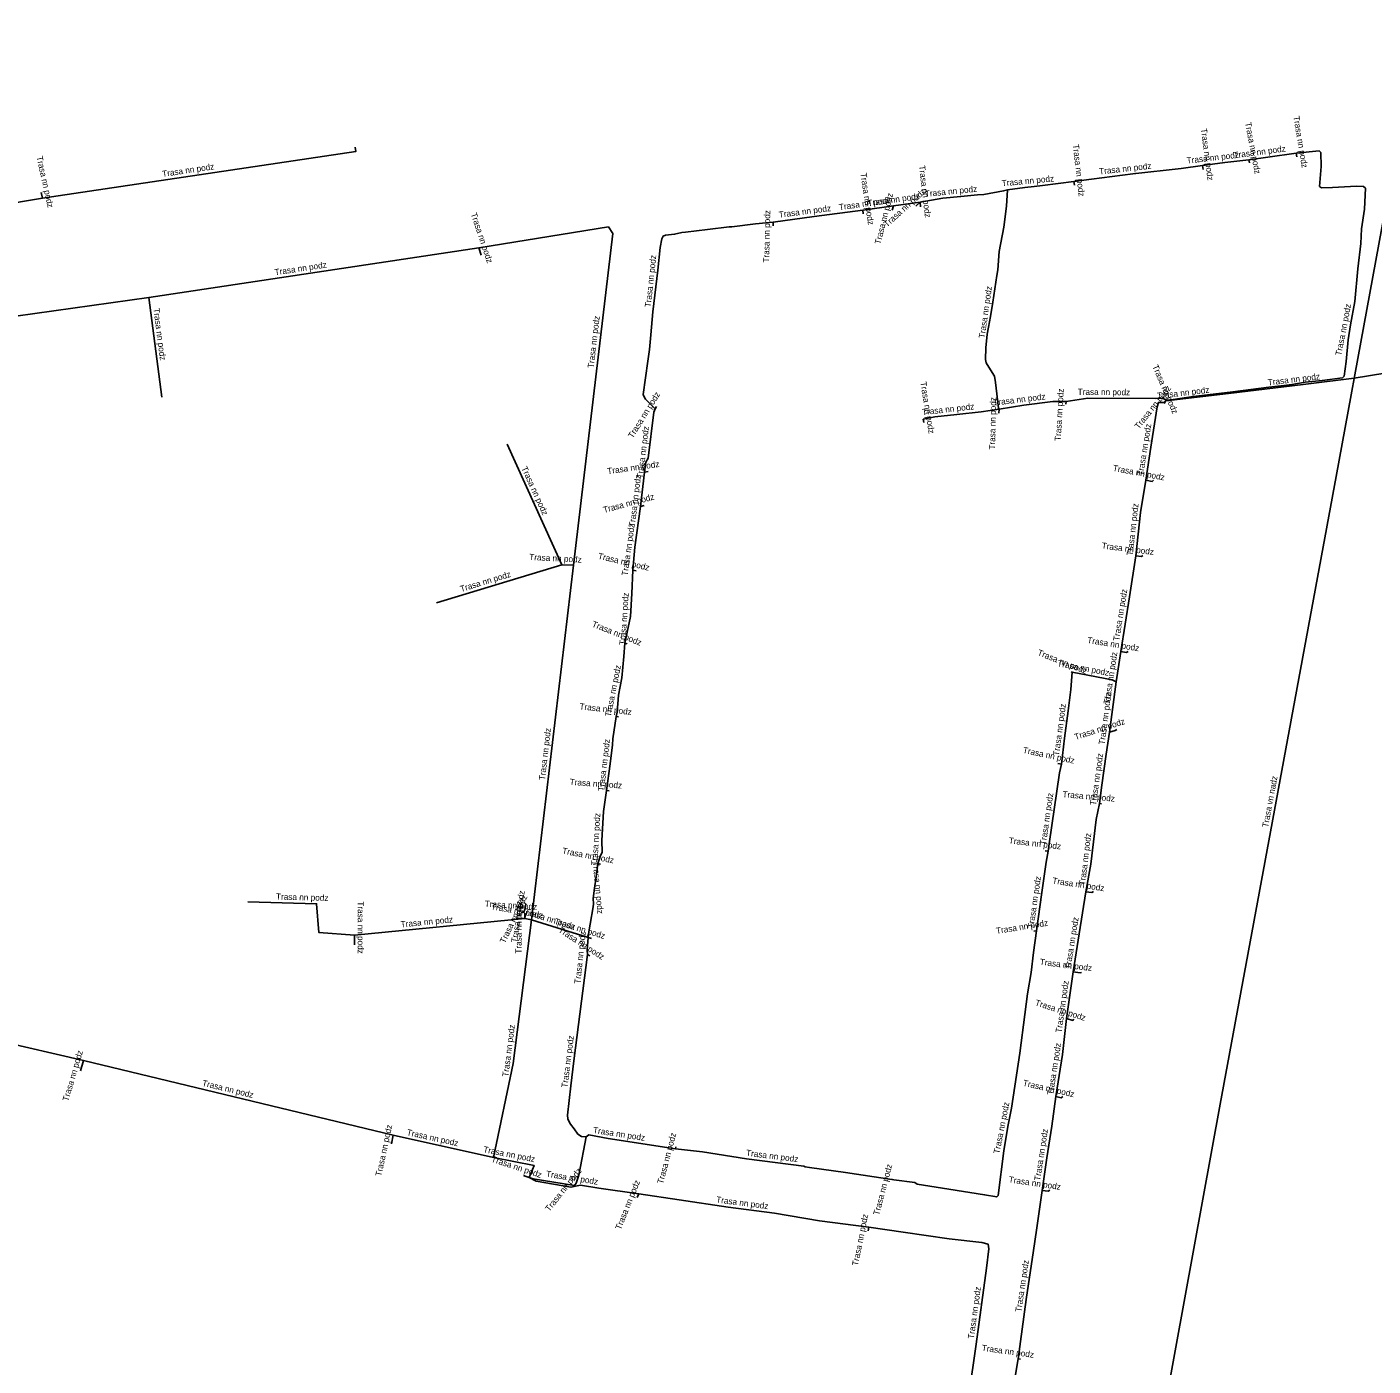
# Model space of a CAD drawing. Extents: x -724876 to -714160, y -1042389 to -1039790.
# Drawn here: x -719777.8 to -719558.8, y -1041292.4 to -1041074.3 of the extents above; entities that cross this region are included whole.
import ezdxf

# ---------------------------------------------------------------- set-up
doc = ezdxf.new("R2010")
doc.units = 0
for name, color, linetype in [('Level 11', 7, 'Continuous'), ('Level 20', 7, 'Continuous'), ('Level 21', 7, 'Continuous')]:
    doc.layers.add(name, color=color, linetype=linetype)

msp = doc.modelspace()

# ---------------------------------------------------------------- linework, layer by layer
at = {"layer": 'Level 11'}
for p, q in [((-719578.95, -1041095.98), (-719578.86, -1041096.47)), ((-719571.25, -1041094.92), (-719571.15, -1041095.5)), ((-719586.5, -1041096.91), (-719586.42, -1041097.55)), ((-719607.44, -1041099.49), (-719607.36, -1041100.13)), ((-719814.8, -1041109), (-719775.3, -1041102.2)), ((-719775.3, -1041102.2), (-719775.5, -1041101.3)), ((-719636.82, -1041103.47), (-719632.47, -1041102.86)), ((-719632.47, -1041102.86), (-719633.18, -1041103.5)), ((-719632.39, -1041103.63), (-719632.47, -1041102.86)), ((-719641.8, -1041104.17), (-719636.82, -1041103.47)), ((-719641.8, -1041104.17), (-719641.71, -1041104.77)), ((-719636.82, -1041103.47), (-719637, -1041104.2)), ((-719656.39, -1041106.15), (-719656.4, -1041106.75)), ((-719758, -1041118.4), (-719704.3, -1041110.3)), ((-719704.3, -1041110.3), (-719703.9, -1041111.5)), ((-719816.9, -1041126.7), (-719758, -1041118.4)), ((-719758, -1041118.4), (-719755.9, -1041134.6)), ((-719608.7, -1041135.31), (-719608.73, -1041135.76)), ((-719592.42, -1041135.09), (-719592.72, -1041135.47)), ((-719675.6, -1041136.52), (-719675.38, -1041136.16)), ((-719631.96, -1041138.18), (-719631.86, -1041138.76)), ((-719619.65, -1041137.23), (-719619.63, -1041136.57)), ((-719690.8, -1041161.9), (-719699.7, -1041142.3)), ((-719677.99, -1041152.42), (-719677.3, -1041146.82)), ((-719677.3, -1041146.82), (-719676.74, -1041146.74)), ((-719677.99, -1041152.42), (-719677.4, -1041152.26)), ((-719690.8, -1041161.9), (-719711.2, -1041168.1)), ((-719688.9, -1041162), (-719695.7, -1041219.7)), ((-719688.9, -1041162), (-719690.8, -1041161.9)), ((-719679.21, -1041162.79), (-719678.7, -1041162.92)), ((-719680.5, -1041174.66), (-719680.12, -1041174.81)), ((-719599.83, -1041176.03), (-719600.58, -1041180.97)), ((-719607.71, -1041179.4), (-719607.89, -1041179.33)), ((-719600.58, -1041180.97), (-719601.67, -1041189.19)), ((-719681.91, -1041186.61), (-719681.57, -1041186.65)), ((-719609.46, -1041194.38), (-719610.07, -1041194.25)), ((-719683.51, -1041198.67), (-719683.07, -1041198.7)), ((-719603.3, -1041200.78), (-719602.93, -1041200.81)), ((-719684.9, -1041210.56), (-719684.51, -1041210.64)), ((-719611.65, -1041208.52), (-719612.13, -1041208.47)), ((-719697, -1041218.48), (-719697.22, -1041218.46)), ((-719696.8, -1041219.5), (-719724.5, -1041222.2)), ((-719695.7, -1041219.7), (-719696.8, -1041219.5)), ((-719695.7, -1041219.7), (-719686.47, -1041222.6)), ((-719613.51, -1041221.49), (-719613.98, -1041221.56)), ((-719724.5, -1041222.2), (-719724.5, -1041223.8)), ((-719686.47, -1041222.6), (-719685.95, -1041222.76)), ((-719686.61, -1041225.35), (-719686.23, -1041225.59)), ((-719607.56, -1041228.21), (-719608.62, -1041235.8)), ((-719768.6, -1041242.6), (-719792.4, -1041237.2)), ((-719768.6, -1041242.6), (-719769.1, -1041244.3)), ((-719718.2, -1041254.8), (-719768.6, -1041242.6)), ((-719718.2, -1041254.8), (-719718.5, -1041256.2)), ((-719701.9, -1041258.4), (-719718.2, -1041254.8)), ((-719672.28, -1041257), (-719672.2, -1041256.7)), ((-719637.09, -1041262.01), (-719637.06, -1041261.87)), ((-719678.26, -1041264.31), (-719678.51, -1041264.92)), ((-719640.8, -1041269.75), (-719640.92, -1041270.36)), ((-719616.52, -1041291.2), (-719616.12, -1041291.25))]:
    msp.add_line(p, q, dxfattribs=at)
for points in [[(-719775.3, -1041102.2), (-719724.3, -1041094.6), (-719724.4, -1041093.9)], [(-719592.42, -1041135.09), (-719591.31, -1041134.98), (-719588.04, -1041134.51), (-719581.58, -1041133.73), (-719575.7, -1041132.98), (-719573.29, -1041132.74), (-719572, -1041132.58), (-719569.78, -1041132.17), (-719567.05, -1041131.89), (-719563.74, -1041131.45), (-719563.47, -1041131.2), (-719563.14, -1041128.79), (-719562.78, -1041125.31), (-719562.44, -1041122.86), (-719561.71, -1041119.03), (-719561.25, -1041113.73), (-719560.76, -1041109.59), (-719560.61, -1041107.22), (-719560.17, -1041104), (-719559.97, -1041100.62), (-719560.29, -1041100.3), (-719561.43, -1041100.29), (-719565.33, -1041100.5), (-719567.17, -1041100.53), (-719567.45, -1041100.3), (-719567.22, -1041097.06), (-719567.25, -1041094.8), (-719567.53, -1041094.49), (-719571.25, -1041094.92)], [(-719578.95, -1041095.98), (-719582.88, -1041096.42), (-719586.5, -1041096.91)], [(-719571.25, -1041094.92), (-719575.9, -1041095.53), (-719578.95, -1041095.98)], [(-719586.5, -1041096.91), (-719590, -1041097.41), (-719597.83, -1041098.28), (-719604.58, -1041099.12), (-719607.44, -1041099.49)], [(-719632.47, -1041102.86), (-719628.75, -1041102.23), (-719625.82, -1041101.95), (-719623.14, -1041101.68), (-719622.09, -1041101.61), (-719618.88, -1041101.03), (-719618.23, -1041100.89)], [(-719618.23, -1041100.89), (-719618.43, -1041103.5), (-719618.85, -1041106.96), (-719619.58, -1041110.92), (-719619.84, -1041113.87), (-719620, -1041114.84), (-719620.61, -1041119.16), (-719621.04, -1041121.51), (-719621.33, -1041123.23), (-719621.55, -1041124.34), (-719621.8, -1041126.58), (-719621.82, -1041128.47), (-719621.7, -1041129.03), (-719620.74, -1041130.63), (-719620.39, -1041131.18), (-719620.21, -1041132.26), (-719619.71, -1041136.39), (-719619.63, -1041136.57)], [(-719607.44, -1041099.49), (-719612.53, -1041100.18), (-719613.89, -1041100.31), (-719615.4, -1041100.48), (-719618.23, -1041100.89)], [(-719656.39, -1041106.15), (-719649.73, -1041105.19), (-719641.8, -1041104.17)], [(-719704.3, -1041110.3), (-719683.2, -1041106.9), (-719682.5, -1041108), (-719688.9, -1041162)], [(-719675.6, -1041136.52), (-719677.17, -1041134.96), (-719677.4, -1041134.59), (-719677.52, -1041134.21), (-719676.78, -1041128.74), (-719676.53, -1041126.85), (-719676.31, -1041124.46), (-719675.95, -1041120.72), (-719675.15, -1041113.94), (-719674.77, -1041110.28), (-719674.5, -1041108.87), (-719674.27, -1041108.41), (-719673.9, -1041108.26), (-719672.43, -1041108.1), (-719671.25, -1041107.84), (-719670.65, -1041107.75), (-719667.05, -1041107.34), (-719663.57, -1041106.89), (-719663.12, -1041106.88), (-719659.28, -1041106.39), (-719656.39, -1041106.15)], [(-719582.27, -1041134.04), (-719570.12, -1041132.54), (-719561.83, -1041131.55), (-719556.83, -1041130.71)], [(-719619.63, -1041136.57), (-719615.6, -1041135.93), (-719610.88, -1041135.34), (-719608.7, -1041135.31)], [(-719608.7, -1041135.31), (-719605.17, -1041134.77), (-719594.16, -1041134.86), (-719592.97, -1041134.81), (-719592.42, -1041135.09)], [(-719592.72, -1041135.47), (-719593.68, -1041135.49), (-719593.87, -1041136.2), (-719594.92, -1041142.74), (-719595.75, -1041148.14)], [(-719582.27, -1041134.04), (-719592.46, -1041135.24), (-719592.72, -1041135.47)], [(-719592.72, -1041135.47), (-719592.72, -1041135.48), (-719592.65, -1041135.65)], [(-719677.3, -1041146.82), (-719677.11, -1041145.23), (-719676.7, -1041144.54), (-719675.81, -1041137.05), (-719675.6, -1041136.52)], [(-719619.63, -1041136.57), (-719622.53, -1041136.99), (-719626.5, -1041137.43), (-719630.05, -1041137.82), (-719631.96, -1041138.18)], [(-719595.75, -1041148.14), (-719596.58, -1041153.42), (-719597.38, -1041160.46)], [(-719595.75, -1041148.14), (-719594.73, -1041148.33), (-719594.47, -1041148.13)], [(-719679.21, -1041162.79), (-719678.91, -1041159.06), (-719677.99, -1041152.42)], [(-719597.38, -1041160.46), (-719598.42, -1041167.12), (-719599.83, -1041176.03)], [(-719597.38, -1041160.46), (-719596.45, -1041160.58), (-719596.25, -1041160.41)], [(-719680.5, -1041174.66), (-719679.62, -1041170.32), (-719679.39, -1041166.6), (-719679.21, -1041162.79)], [(-719681.91, -1041186.61), (-719681.79, -1041185.91), (-719681.58, -1041183.12), (-719681.02, -1041180.3), (-719680.68, -1041176.84), (-719680.5, -1041174.66)], [(-719599.83, -1041176.03), (-719598.91, -1041176.18), (-719598.59, -1041176.02)], [(-719609.46, -1041194.38), (-719608.97, -1041190.17), (-719608.37, -1041185.68), (-719607.94, -1041182.22), (-719607.71, -1041179.4)], [(-719600.58, -1041180.97), (-719601.22, -1041180.63), (-719607.71, -1041179.4)], [(-719683.51, -1041198.67), (-719682.89, -1041194.31), (-719682.53, -1041191.23), (-719682.48, -1041190.23), (-719681.91, -1041186.61)], [(-719601.67, -1041189.19), (-719602.18, -1041192.76), (-719602.89, -1041197.8), (-719603.3, -1041200.78)], [(-719601.67, -1041189.19), (-719600.7, -1041188.88), (-719600.43, -1041188.73)], [(-719611.65, -1041208.52), (-719611.47, -1041207.35), (-719609.79, -1041195.78), (-719609.46, -1041194.38)], [(-719684.9, -1041210.56), (-719684.56, -1041209.43), (-719684.24, -1041208.68), (-719684.26, -1041206.81), (-719683.99, -1041202.11), (-719683.51, -1041198.67)], [(-719603.3, -1041200.78), (-719603.84, -1041203.41), (-719604.7, -1041210.65), (-719605.5, -1041215.14)], [(-719686.47, -1041222.6), (-719686.36, -1041221.65), (-719686.14, -1041220.42), (-719685.66, -1041217.59), (-719685.62, -1041217.14), (-719685.7, -1041216.24), (-719685.44, -1041214.54), (-719685.18, -1041212.72), (-719684.9, -1041210.56)], [(-719613.51, -1041221.49), (-719612.65, -1041215.25), (-719611.93, -1041210.31), (-719611.65, -1041208.52)], [(-719724.5, -1041222.2), (-719730.3, -1041221.8), (-719730.7, -1041217.1), (-719741.9, -1041216.8)], [(-719696.93, -1041216.91), (-719696.61, -1041217.17), (-719696.72, -1041217.9)], [(-719605.5, -1041215.14), (-719606.58, -1041221.99), (-719607.56, -1041228.21)], [(-719605.5, -1041215.14), (-719604.55, -1041215.28), (-719604.25, -1041215.13)], [(-719696.72, -1041217.9), (-719696.91, -1041218.3), (-719697, -1041218.48)], [(-719697, -1041218.48), (-719696.8, -1041218.7), (-719696.8, -1041219.5)], [(-719701.9, -1041258.4), (-719698.7, -1041243.1), (-719695.7, -1041219.7)], [(-719637.09, -1041262.01), (-719636.76, -1041262.05), (-719633.33, -1041262.51), (-719632.96, -1041262.78), (-719627.79, -1041263.57), (-719621.98, -1041264.47), (-719620.01, -1041264.83), (-719619.78, -1041264.62), (-719618.86, -1041257.34), (-719618.18, -1041253.36), (-719617.6, -1041250.39), (-719616.24, -1041241.44), (-719615.43, -1041235.14), (-719614.99, -1041231.75), (-719614.41, -1041228.27), (-719614, -1041225.03), (-719613.51, -1041221.49)], [(-719686.61, -1041225.35), (-719686.68, -1041224.63), (-719686.47, -1041222.6)], [(-719686.84, -1041255.04), (-719687.56, -1041254.99), (-719688.16, -1041254.6), (-719688.77, -1041253.77), (-719689.39, -1041252.98), (-719689.61, -1041252.61), (-719689.82, -1041252.11), (-719689.86, -1041251.52), (-719689.31, -1041246.76), (-719688.81, -1041242.69), (-719686.61, -1041225.35)], [(-719607.56, -1041228.21), (-719606.42, -1041228.35), (-719606.18, -1041228.27)], [(-719608.62, -1041235.8), (-719609.3, -1041241.66), (-719610.37, -1041248.48)], [(-719608.62, -1041235.8), (-719607.63, -1041236.11), (-719607.44, -1041235.92)], [(-719610.37, -1041248.48), (-719611.06, -1041253.3), (-719611.85, -1041258.45), (-719612.61, -1041263.78)], [(-719610.37, -1041248.48), (-719609.49, -1041248.68), (-719609.26, -1041248.51)], [(-719696.09, -1041261.69), (-719695.42, -1041261.91), (-719688.73, -1041262.99), (-719688.44, -1041262.62), (-719688.13, -1041261.62), (-719687.97, -1041261.03), (-719686.84, -1041255.04)], [(-719686.84, -1041255.04), (-719686.38, -1041254.73), (-719683.22, -1041255.32), (-719672.28, -1041257)], [(-719696.09, -1041261.69), (-719695.3, -1041259.7), (-719701.9, -1041258.4)], [(-719672.28, -1041257), (-719667.91, -1041257.48), (-719660.72, -1041258.64), (-719651.4, -1041259.82), (-719651.19, -1041259.93), (-719650.47, -1041260.05), (-719644.62, -1041260.88), (-719637.09, -1041262.01)], [(-719696.99, -1041261.37), (-719696.57, -1041261.53), (-719696.09, -1041261.69)], [(-719678.26, -1041264.31), (-719684.77, -1041263.39), (-719687.73, -1041262.93), (-719689.3, -1041263.27), (-719694.96, -1041262.26), (-719696.09, -1041261.69)], [(-719640.8, -1041269.75), (-719648.86, -1041268.72), (-719656.18, -1041267.48), (-719663.7, -1041266.5), (-719671.7, -1041265.3), (-719678.26, -1041264.31)], [(-719612.61, -1041263.78), (-719613.55, -1041270.23), (-719614, -1041273.58), (-719615.19, -1041281.56), (-719616.52, -1041291.2)], [(-719612.61, -1041263.78), (-719611.62, -1041263.92), (-719611.34, -1041263.76)], [(-719626.73, -1041310.38), (-719626.61, -1041308.97), (-719625.98, -1041307.8), (-719625.59, -1041304.87), (-719624.53, -1041297.11), (-719623.34, -1041288.81), (-719621.64, -1041276.46), (-719621.31, -1041273.31), (-719621.4, -1041272.55), (-719622.44, -1041272.28), (-719627.73, -1041271.64), (-719635.22, -1041270.6), (-719640.8, -1041269.75)], [(-719616.52, -1041291.2), (-719616.98, -1041294.05), (-719617.64, -1041298.87), (-719619.07, -1041308.2), (-719619.55, -1041311.4)]]:
    msp.add_lwpolyline(points, dxfattribs=at)
at = {"layer": 'Level 21'}
for p, q in [((-719564.76, -1041147.56), (-719545.11, -1041040.19)), ((-719583.65, -1041249.73), (-719564.76, -1041147.56)), ((-719602.49, -1041353.09), (-719583.65, -1041249.73))]:
    msp.add_line(p, q, dxfattribs=at)

# ---------------------------------------------------------------- texts
at = {"layer": 'Level 20'}
for s, rotation, p in [('Trasa nn podz', 280.7736, (-719579.59, -1041089.95)), ('Trasa nn podz', 279.5105, (-719571.74, -1041088.93)), ('Trasa nn podz', 277.5709, (-719586.79, -1041090.93)), ('Trasa nn podz', 276.5549, (-719607.62, -1041093.51)), ('Trasa nn podz', 7.4646, (-719581.4, -1041095.74)), ('Trasa nn podz', 282.5288, (-719776.28, -1041095.5)), ('Trasa nn podz', 8.4758, (-719755.74, -1041098.78)), ('Trasa nn podz', 6.304, (-719603.28, -1041098.37)), ('Trasa nn podz', 6.3754, (-719589.04, -1041096.6)), ('Trasa nn podz', 278.4201, (-719642.18, -1041098.18)), ('Trasa nn podz', 276.6839, (-719632.66, -1041096.95)), ('Trasa nn podz', 5.3846, (-719619.14, -1041100.3)), ('Trasa nn podz', 41.8036, (-719637.85, -1041107)), ('Trasa nn podz', 5.6259, (-719631.65, -1041102.02)), ('Trasa nn podz', 7.9369, (-719645.61, -1041104.19)), ('Trasa nn podz', 7.9582, (-719640.94, -1041103.54)), ('Trasa nn podz', 75.9083, (-719638.92, -1041109.81)), ('Trasa nn podz', 288.4349, (-719705.61, -1041104.78)), ('Trasa nn podz', 88.5821, (-719657.05, -1041112.72)), ('Trasa nn podz', 7.3517, (-719655.4, -1041105.42)), ('Trasa nn podz', 83.9902, (-719676.3, -1041120.03)), ('Trasa nn podz', 8.5777, (-719737.44, -1041114.79)), ('Trasa nn podz', 81.9201, (-719621.96, -1041125.07)), ('Trasa nn podz', 277.386, (-719757.26, -1041120.2)), ('Trasa nn podz', 79.1161, (-719563.93, -1041127.92)), ('Trasa nn podz', 83.2409, (-719685.6, -1041129.93)), ('Trasa nn podz', 293.1485, (-719594.7, -1041129.59)), ('Trasa nn podz', 6.8433, (-719575.83, -1041132.73)), ('Trasa nn podz', 58.1527, (-719679.23, -1041141.41)), ('Trasa nn podz', 279.3193, (-719632.44, -1041132.19)), ('Trasa nn podz', 86.6859, (-719609.58, -1041141.78)), ('Trasa nn podz', 359.511, (-719606.83, -1041134.25)), ('Trasa nn podz', 51.5788, (-719596.87, -1041139.9)), ('Trasa nn podz', 6.702, (-719593.84, -1041134.9)), ('Trasa nn podz', 6.3799, (-719632.1, -1041137.55)), ('Trasa nn podz', 88.6921, (-719620.28, -1041143.17)), ('Trasa nn podz', 7.0115, (-719620.49, -1041136.02)), ('Trasa nn podz', 83.2067, (-719677.6, -1041147.89)), ('Trasa nn podz', 80.8985, (-719596.18, -1041147.46)), ('Trasa nn podz', 294.4219, (-719697.39, -1041146.17)), ('Trasa nn podz', 8.0298, (-719683.31, -1041147.17)), ('Trasa nn podz', 349.3192, (-719601.16, -1041146.61)), ('Trasa nn podz', 82.8926, (-719678.92, -1041155.8)), ('Trasa nn podz', 14.9854, (-719683.9, -1041153.48)), ('Trasa nn podz', 83.5277, (-719597.88, -1041160.47)), ('Trasa nn podz', 82.1166, (-719680.07, -1041163.75)), ('Trasa nn podz', 356.9872, (-719696.1, -1041161.12)), ('Trasa nn podz', 346.7472, (-719684.96, -1041160.93)), ('Trasa nn podz', 352.8445, (-719602.96, -1041159.26)), ('Trasa nn podz', 16.9052, (-719707.16, -1041166.35)), ('Trasa nn podz', 86.4313, (-719680.42, -1041175.01)), ('Trasa nn podz', 80.9825, (-719600.08, -1041174.38)), ('Trasa nn podz', 338.2758, (-719685.97, -1041171.95)), ('Trasa nn podz', 350.7299, (-719605.32, -1041174.63)), ('Trasa nn podz', 338.4661, (-719613.46, -1041176.59)), ('Trasa nn podz', 349.2924, (-719610.19, -1041178.42)), ('Trasa nn podz', 81.3802, (-719601.64, -1041184.64)), ('Trasa nn podz', 78.6627, (-719682.81, -1041186.72)), ('Trasa nn podz', 82.4661, (-719602.44, -1041191.25)), ('Trasa nn podz', 353.6964, (-719687.94, -1041185.44)), ('Trasa nn podz', 82.3694, (-719609.86, -1041193.06)), ('Trasa nn podz', 83.2786, (-719693.53, -1041197.03)), ('Trasa nn podz', 17.9532, (-719607.17, -1041190.45)), ('Trasa nn podz', 83.3388, (-719683.92, -1041198.83)), ('Trasa nn podz', 348.0349, (-719615.81, -1041192.53)), ('Trasa nn podz', 81.9639, (-719603.86, -1041201.14)), ('Trasa nn podz', 355.9331, (-719689.53, -1041197.74)), ('Trasa vn nadz', 79.524, (-719575.84, -1041204.74)), ('Trasa nn podz', 81.7208, (-719612.01, -1041207.59)), ('Trasa nn podz', 355.0702, (-719609.33, -1041199.75)), ('Trasa nn podz', 86.6886, (-719685, -1041210.9)), ('Trasa nn podz', 83.1897, (-719605.62, -1041214.14)), ('Trasa nn podz', 349.1417, (-719690.78, -1041208.93)), ('Trasa nn podz', 353.4226, (-719618.08, -1041207.28)), ('Trasa nn podz', 275.2574, (-719685.75, -1041210.28)), ('Trasa nn podz', 81.7173, (-719614.01, -1041221.15)), ('Trasa nn podz', 351.4075, (-719611, -1041213.8)), ('Trasa nn podz', 358.4657, (-719737.31, -1041216.42)), ('Trasa nn podz', 270, (-719724, -1041216.71)), ('Trasa nn podz', 356.4677, (-719703.35, -1041217.58)), ('Trasa nn podz', 349.6952, (-719702.35, -1041217.98)), ('Trasa nn podz', 64.3649, (-719700.03, -1041223.64)), ('Trasa nn podz', 81.5111, (-719698.06, -1041223.48)), ('Trasa nn podz', 89.7142, (-719697.33, -1041225.23)), ('Trasa nn podz', 5.5672, (-719716.96, -1041220.96)), ('Trasa nn podz', 342.5499, (-719696.93, -1041218.79)), ('Trasa nn podz', 81.0798, (-719607.99, -1041227.81)), ('Trasa nn podz', 343.0988, (-719692.08, -1041220.38)), ('Trasa nn podz', 327.0449, (-719691.43, -1041221.63)), ('Trasa nn podz', 9.0287, (-719620.03, -1041222.02)), ('Trasa nn podz', 84.0072, (-719687.77, -1041230.17)), ('Trasa nn podz', 352.9804, (-719613.04, -1041227.03)), ('Trasa nn podz', 81.9905, (-719609.46, -1041238.16)), ('Trasa nn podz', 342.6098, (-719613.85, -1041233.63)), ('Trasa nn podz', 82.6942, (-719699.49, -1041245.32)), ('Trasa nn podz', 82.7929, (-719689.87, -1041247.1)), ('Trasa nn podz', 73.6105, (-719771.1, -1041249.34)), ('Trasa nn podz', 81.0865, (-719610.84, -1041248.29)), ('Trasa nn podz', 346.3925, (-719749.39, -1041246.73)), ('Trasa nn podz', 347.1446, (-719615.81, -1041246.72)), ('Trasa nn podz', 78.9237, (-719619.57, -1041257.88)), ('Trasa nn podz', 77.9052, (-719720.16, -1041261.54)), ('Trasa nn podz', 347.5457, (-719716.08, -1041254.76)), ('Trasa nn podz', 351.2546, (-719685.75, -1041254.42)), ('Trasa nn podz', 81.2563, (-719612.94, -1041262.26)), ('Trasa nn podz', 348.8571, (-719703.62, -1041257.55)), ('Trasa nn podz', 75.2564, (-719674.32, -1041262.8)), ('Trasa nn podz', 341.6369, (-719702.35, -1041259.08)), ('Trasa nn podz', 352.8008, (-719660.84, -1041258.12)), ('Trasa nn podz', 51.3787, (-719692.81, -1041267.3)), ('Trasa nn podz', 351.117, (-719693.4, -1041261.54)), ('Trasa nn podz', 75.2173, (-719639.16, -1041267.89)), ('Trasa nn podz', 68.1497, (-719681.19, -1041270.27)), ('Trasa nn podz', 351.6441, (-719618.1, -1041262.46)), ('Trasa nn podz', 352.537, (-719665.7, -1041265.73)), ('Trasa nn podz', 78.5279, (-719642.6, -1041276.12)), ('Trasa nn podz', 81.5117, (-719616.01, -1041283.63)), ('Trasa nn podz', 82.1787, (-719623.73, -1041287.99)), ('Trasa nn podz', 352.3116, (-719622.48, -1041289.89))]:
    msp.add_text(s, height=1, rotation=rotation, dxfattribs=at).set_placement(p)

doc.saveas('drawing.dxf')
